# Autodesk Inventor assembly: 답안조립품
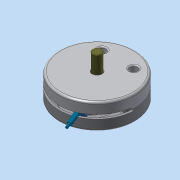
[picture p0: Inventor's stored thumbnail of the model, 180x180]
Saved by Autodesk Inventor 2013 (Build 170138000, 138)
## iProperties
Created: 2015-04
Part Number: 답안조립품
Document SubType Name: Assembly
Designer: Administrator
Author: Administrator
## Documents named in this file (10)
- C:\Users\Administrator\Desktop\450406V1011\답안조립품.iam
- C:\Users\Administrator\Desktop\450406V1011\본체.ipt
- C:\Users\Administrator\Desktop\450406V1011\M 10 x 35.ipt
- C:\Users\Administrator\Desktop\450406V1011\덮개.ipt
- C:\Users\Administrator\Desktop\450406V1011\멈춤링.ipt
- C:\Users\Administrator\Desktop\450406V1011\베어링62_22.ipt
- C:\Users\Administrator\Desktop\450406V1011\슬라이더.ipt
- C:\Users\Administrator\Desktop\450406V1011\슬라이더2.ipt
- C:\Users\Administrator\Desktop\450406V1011\축.ipt
- C:\Users\Administrator\Desktop\450406V1011\평행핀.ipt
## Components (2 placed, 1 different names)
1. M 10 x 35:2
2. M 10 x 35:3
